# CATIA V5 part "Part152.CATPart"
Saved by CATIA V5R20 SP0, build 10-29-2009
Part number: DFA 084700-2 comprimido
Revision: ANY
Definition: UNKNOWN
Nomenclature: DFA 084700-2 comprimido
Source: Unknown
Bounding box of the stored display mesh (mm): x -2.45 to 2.45, y 0 to 4.72, z -2.45 to 2.45
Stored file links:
  C:\Users\Utente\Desktop\IO LAVORO\3D X SITO CF\CUMSA\3D files FA\FA 105706-21\Part152.CATPart
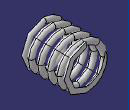
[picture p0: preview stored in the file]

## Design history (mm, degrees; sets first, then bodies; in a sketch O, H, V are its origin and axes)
Body1 "Cortar-Extruir1" (main body)
  Solid1: solid without history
